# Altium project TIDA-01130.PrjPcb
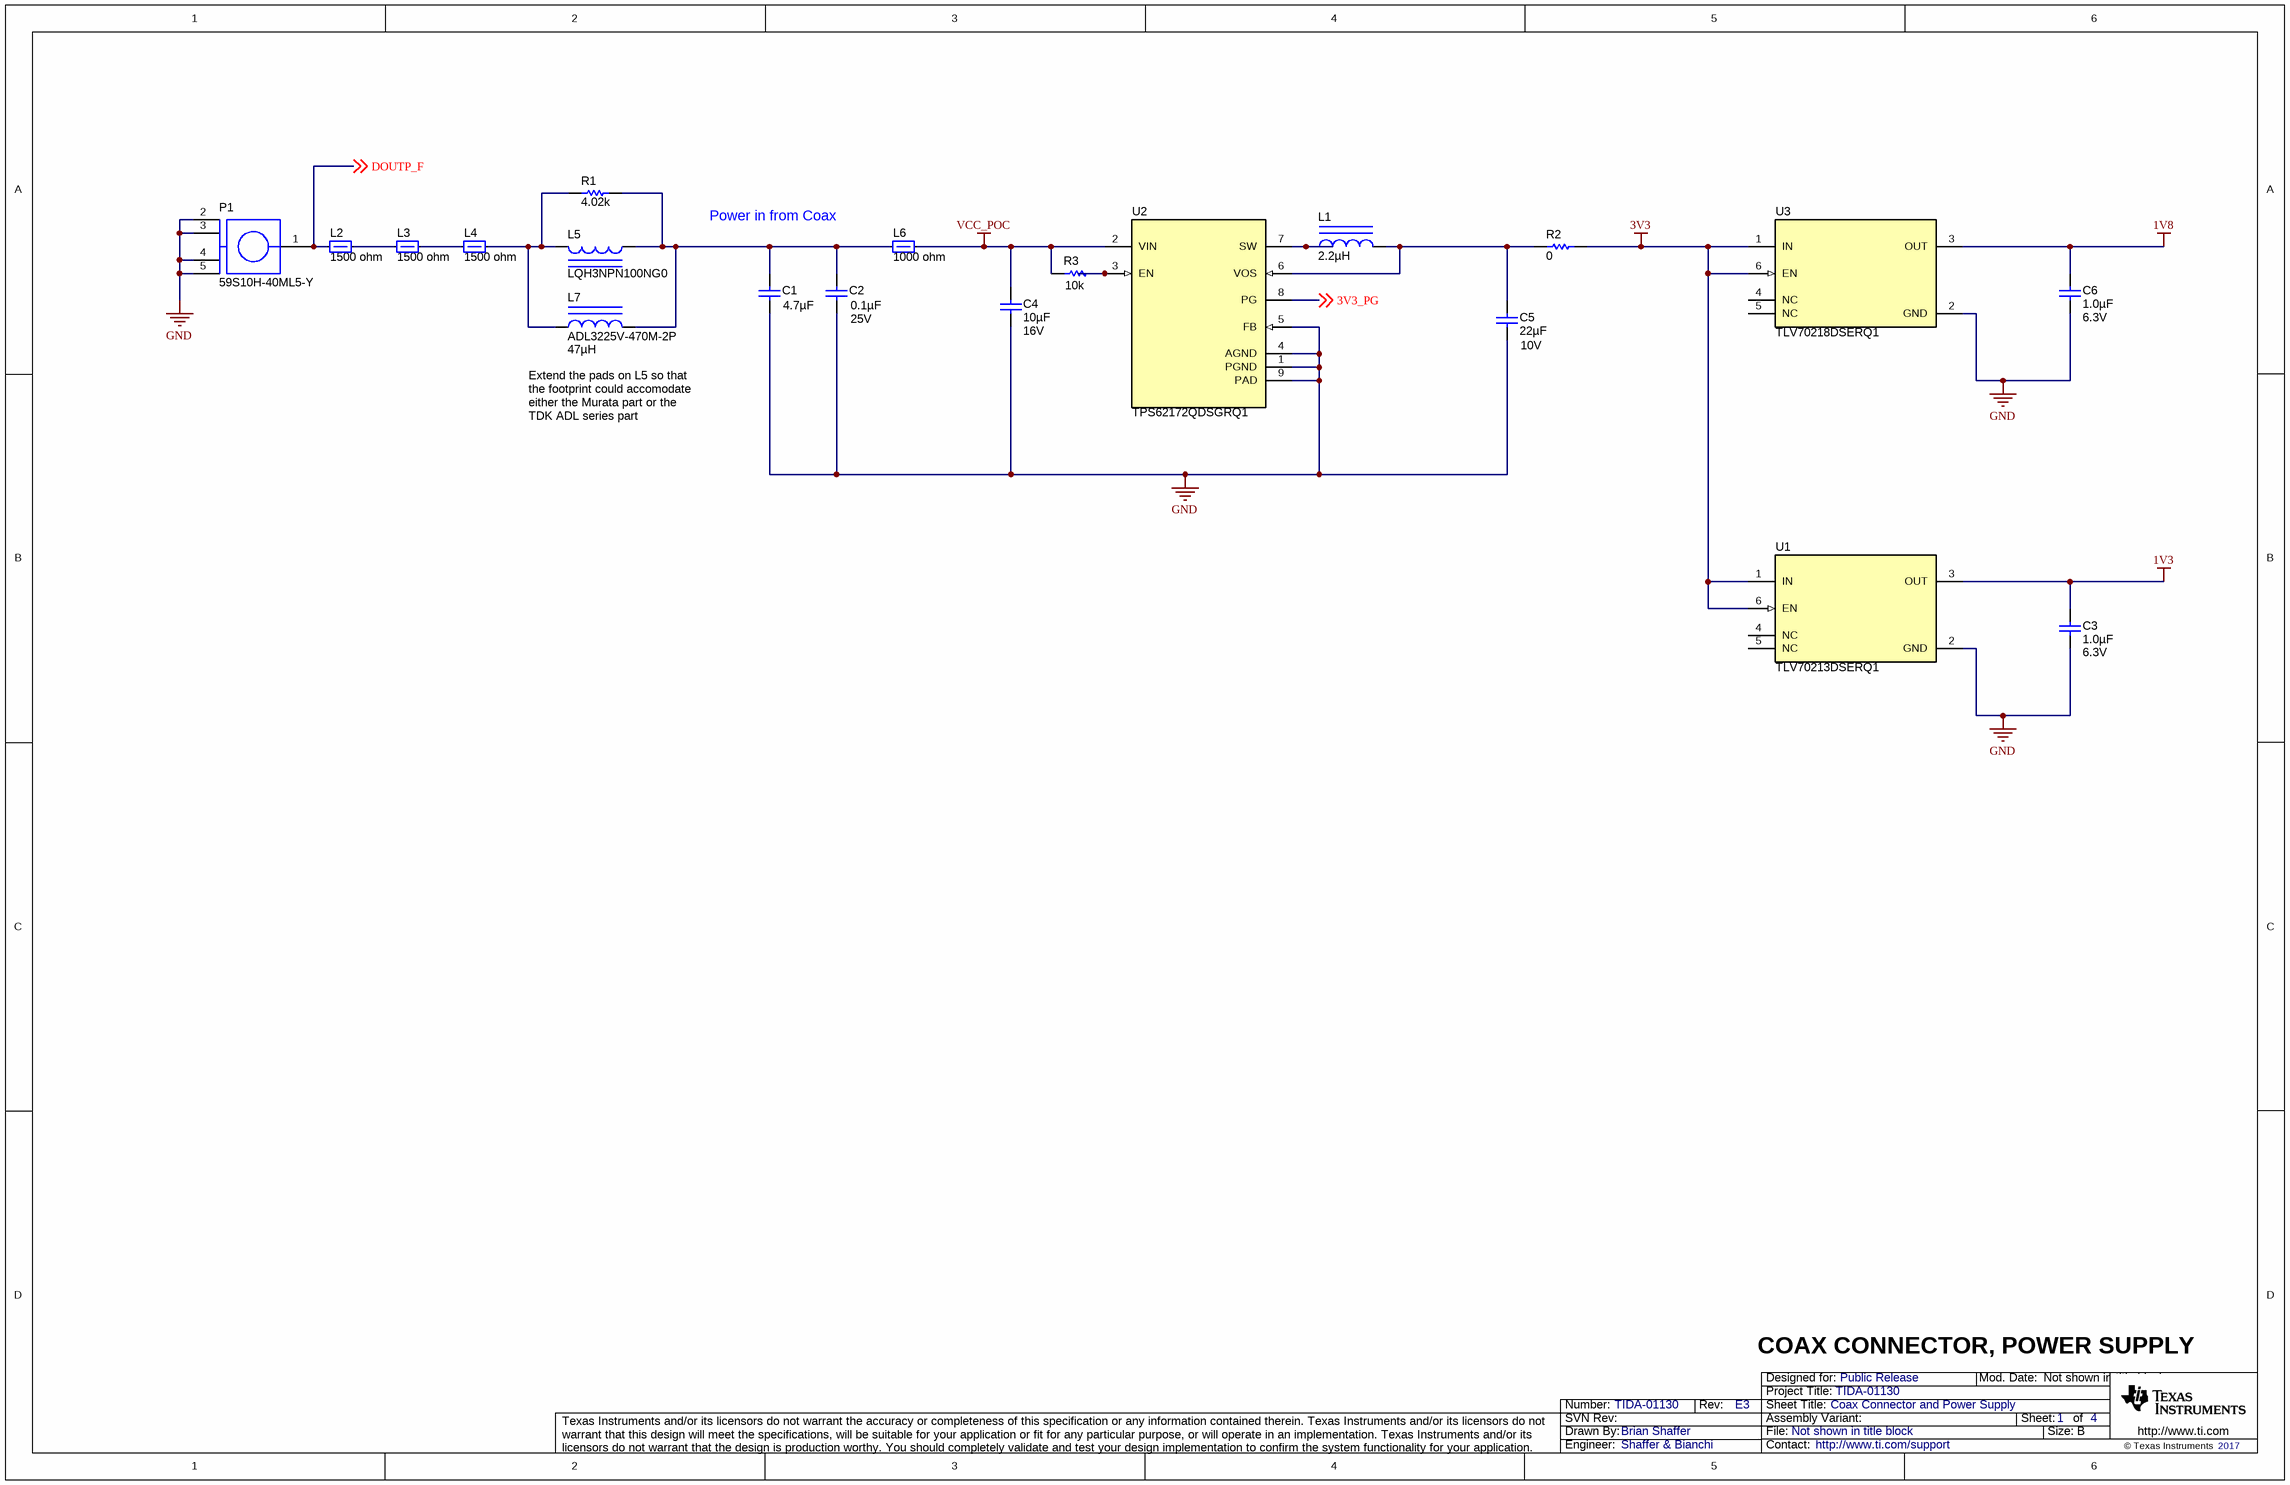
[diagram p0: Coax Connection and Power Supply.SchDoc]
CopyrightYear: 2017; PCB_Layout: Krypton Solutions; PCB_Rev: E3; PRJ_Customer: Public Release; PRJ_Engineer: Shaffer & Bianchi; PRJ_Number: TIDA-01130; PRJ_Title: TIDA-01130; SCH_Rev: E3; TechSupport: http://www.ti.com/support
4 sheets, 92 parts. Net scope: global (net labels, ports and power ports of the same name join across sheets).
Board file: TIDA-01130.PcbDoc
Sheets:
  Coax Connection and Power Supply.SchDoc
  Imager.SchDoc
  Serializer.SchDoc
  HDWR.SchDoc

## Sheet Coax Connection and Power Supply.SchDoc: Coax Connector and Power Supply
size 431 x 279 mm; Date: Not shown in title block; ApprovedBy: Not shown in title block; CheckedBy: Not shown in title block; Author: Not shown in title block; CompanyName: Not shown in title block; DrawnBy: Brian Shaffer; Engineer: Not shown in title block; Organization: Not shown in title block; Address1: Not shown in title block; Address2: Not shown in title block; Address3: Not shown in title block; Address4: Not shown in title block; DocumentNumber: 1; Revision: Use project parameter SCH_Rev; SheetNumber: 1; SheetTotal: 4; PageSetup: Record=PageOptions¦CenterHorizontal=True¦CenterVertical=True¦PrintScale=0.62¦XCorrection=1.00¦YCorrection=1.00¦PrintKind=0¦BorderSize=5000000¦LeftOffset=0¦BottomOffset=0¦Orientation=2¦PaperLength=1000¦PaperWidth=1000¦Scale=100¦PaperSource=15¦PrintQuality=600¦MediaType=1¦DitherType=10¦PrintScaleMode=1¦PaperKind=Letter (8.5 x 11")¦PaperIndex=1

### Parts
C1  value 4.7µF  [0805L]  (hidden comment: CGA4J1X7R1E475M125AC)
C2  value 0.1µF  VDC_V: 25V  [0402L]  (hidden comment: C1005X7R1E104K050BB)
C3  value 1.0µF  VDC_V: 6.3V  [0402L]  (hidden comment: CL05B105KQ5NQNC)
C4  ValueDisplayed: 10µF  Value2: 16V  [0805L]  (hidden comment: CL21B106KOQNNNE)
C5  ValueDisplayed: 22µF  VDC_V: 10V  [1206L]  (hidden comment: GRM31CR71A226KE15L)
C6  value 1.0µF  VDC_V: 6.3V  [0402L]  (hidden comment: CL05B105KQ5NQNC)
L1  ValueDisplayed: 2.2µH  [XPL2010]  (hidden comment: XPL2010-222MLB)
L2  value 1500 ohm  [0603L]  (hidden comment: BLM18HE152SN1D)
L3  value 1500 ohm  [0603L]  (hidden comment: BLM18HE152SN1D)
L4  value 1500 ohm  [0603L]  (hidden comment: BLM18HE152SN1D)
L5  LQH3NPN100NG0  [LQH3NP_G0]
L6  value 1000 ohm  [0603L]  (hidden comment: BLM18AG102SN1D)
L7  ADL3225V-470M-2P  ValueDisplayed: 47µH  [ADL3225V]
P1  59S10H-40ML5-Y  [59S10H-40ML5-Y]
R1  ValueDisplayed: 4.02k  [0603L]  (hidden comment: CRCW06034K02FKEA)
R2  value 0  [0402L]  (hidden comment: CRCW04020000Z0ED)
R3  value 10k  [0402L]  (hidden comment: CRCW040210K0JNED)
U1  TLV70213DSERQ1  [DSE0006A]
U2  TPS62172QDSGRQ1  [DSG0008A]
U3  TLV70218DSERQ1  [DSE0006A]

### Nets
1V3: C3.1 U1.3(OUT)
1V8: C6.1 U3.3(OUT)
3V3: R2.1 U1.1(IN) U1.6(EN) U3.1(IN) U3.6(EN)
GND: C1.2 C2.2 C3.2 C4.2 C5.2 C6.2 P1.2 P1.3 P1.4 P1.5 U1.2(GND) U2.1(PGND) U2.4(AGND) U2.5(FB) U2.9(PAD) U3.2(GND)
VCC_POC: C4.1 L6.2 R3.2 U2.2(VIN)
3V3_PG: U2.8(PG) ; off-sheet 3V3_PG
DOUTP_F: L2.1 P1.1 ; off-sheet DOUTP_F
NetC1_1: C1.1 C2.1 L5.1 L6.1 L7.2 R1.1
NetC5_1: C5.1 L1.2 R2.2 U2.6(VOS)
NetL1_1: L1.1 U2.7(SW)
NetL2_2: L2.2 L3.1
NetL3_2: L3.2 L4.1
NetL4_2: L4.2 L5.2 L7.1 R1.2
NetR3_1: R3.1 U2.3(EN)

Not connected (* = marked no-connect by the designer): U1 4(NC) 5(NC); U3 4(NC) 5(NC)

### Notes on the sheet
- (near L6) Power in from Coax
- (near L7) Extend the pads on L5 so that the footprint could accomodate either the Murata part or the TDK ADL series part
- COAX CONNECTOR, POWER SUPPLY

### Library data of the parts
C1 = C2012X7R1E474K: CAP, CERM, 4.7uF, 25V, +/-20%, X7R, 0805; Manufacturer: TDK Corporation; Tolerance_%: ±20%
C2 = C1005X7R1E103K: CAP, CERM, 0.1uF, 25V, +/-10%, X7R, 0402; Manufacturer: TDK Corporation; Tolerance_%: ±10%
C3 C6 = Capacitor: CAP CER 1UF 6.3V 10% X7R 0402; Manufacturer: Samsung Electro-Mechanics America, Inc; Polarized: N; U/M: EA
C4 = CL21B106KOQNNNE: CAP, CERM, 10 µF, 16 V, +/- 10%, X7R, 0805; Manufacturer: Samsung Electro-Mechanics; Polarized: N; CompType: Capacitor; Value: 10uF; U/M: EA; Cap_F: 0.00001; Tolerance_%: 10; Value1: Unknown; VDC_V: 16; TaMin_C: -55; TaMax_C: 125; Cap_Case: 0805; SizeArea_mm2: 2.5; SizeAreaWB_mm2: 6.75; SizeX_mm: 2; SizeY_mm: 1.25; SizeZ_mm: 1.45; AEC Category: Q200
C5 = GRM31CR71A226KE15L: CAP, CERM, 22uF, 10V, +/-10%, X7R, 1206; Manufacturer: MuRata; Polarized: N; CompType: Capacitor; U/M: EA; Cap_F: 0.000022; Tolerance_%: 10; Value1: Unknown; TaMin_C: -55; TaMax_C: 125; Cap_Case: 1206
L1 = XPL2010-222MLB: Inductor, Shielded, Composite, 2.2 µH, 1.3 A, 0.16 ohm, SMD; Manufacturer: Coilcraft; Value: 2.2uH; Ind_H: 2.2E-6; Imax_A: 1.3; Irms: 1.3A @ 40C rise; Isat: 1.35A @ 30% inductance drop; DCR_ohm: 0.16; Value2: 1.3A; SizeAreaWB_mm2: 8.7; SizeArea_mm2: 3.8; SizeX_mm: 2; SizeY_mm: 1.9; SizeZ_mm: 1; AEC Category: Q200; Green_Lifecycle: Not Set; Green_REACh: Incomplete
L2 L3 = BLM18HE152SN1D: Ferrite Bead, 1500 ohm @ 100 MHz, 0.5 A, 0603; Manufacturer: MuRata; Imax_A: 0.5; Value1: 0.5 ohm; Value2: 0.5A; ZTyp@100MHz_Ohm: 1500; SizeAreaWB_mm2: 4.68; SizeArea_mm2: 1.28; SizeX_mm: 1.6; SizeY_mm: 0.8; SizeZ_mm: 1
L4 = BLM18HE152SN1D: Ferrite Bead, 1500 ohm @ 100 MHz, 0.5 A, 0603; Manufacturer: MuRata; Value1: 0.5 ohm; Value2: 0.5A; SizeArea_mm2: 1.28; SizeX_mm: 1.6; SizeY_mm: 0.8; SizeZ_mm: 1; Imax_A: 0.5; SizeAreaWB_mm2: 4.68; ZTyp@100MHz_Ohm: 1500
L5 = LQH3NPN100NG0: Inductor, Wirewound, Ferrite, 10 µH, 0.5 A, 0.57 ohm, SMD; Manufacturer: MuRata; Value: 10uH; Ind_H: 10.0E-6; ValueDisplayed: 10µH; Imax_A: 0.5; Irms: 0.63A @ 40C rise; Isat: 0.5A @ 30% inductance drop; DCR_ohm: 0.57; Value2: 0.5A
L6 = BLM18AG102SN1D: Ferrite Bead, 1000 ohm @ 100 MHz, 0.4 A, 0603; Manufacturer: MuRata; Imax_A: 0.4; DCR_ohm: 0.5; Value1: 0.5 ohm; Value2: 0.4A; ZTyp@100MHz_Ohm: 1000
L7 = ADL3225V-470M-2P: Inductor, Wirewound, 47 µH, 0.35 A, 1.3 ohm, SMD; Manufacturer: TDK; Value: 47uH; Ind_H: 47.0E-6; Imax_A: 0.35; Irms: 0.385A @ 40C rise; Isat: 0.35A @ 30% inductance drop; DCR_ohm: 1.3; Value1: 1.3 ohm; Value2: 0.35A; SizeAreaWB_mm2: 14.7; SizeArea_mm2: 8; SizeX_mm: 3.2; SizeY_mm: 2.5; SizeZ_mm: 2.4; AEC Category: Q200
P1 = 59S10H-40ML5-Y: Straight Plug PCB; Manufacturer: Rosenberger; SymbolVersion: use current date i.e. 2008-05-20; SymbolCreator: Use a-id; CompType: SMA connector; U/M: EA, IN, or GM
R1 = CRCW06034K02FKEA: RES, 4.02 k, 1%, 0.1 W, 0603; Manufacturer: Vishay-Dale; CompType: Resistor; Value: 4.02k; Res_ohm: 4020; Value_Code: 4k02; Tolerance_%: 1; Power_W: 0.1; Value2: 0.1W; VDC_V: 75; TempCo: 100 ppm/C; EIA_Code: E96; U/M: EA
R2 = CRCW04020000Z0ED: RES, 0 ohm, 5%, 0.063W, 0402; Manufacturer: Vishay-Dale; CompType: Resistor; Value_Code: 0000; Tolerance_%: 5; Power_W: 0.063; VDC_V: 50; TempCo: 200 ppm/C; EIA_Code: E24; U/M: EA
R3 = CRCW040210K0JNED: RES, 10k ohm, 5%, 0.063W, 0402; Manufacturer: Vishay-Dale; CompType: Resistor; Res_ohm: 10000; Value_Code: 10k0; Tolerance_%: 5; Power_W: 0.063; VDC_V: 50; TempCo: 200 ppm/C; EIA_Code: E24; U/M: EA
U1 = TLV70213DSERQ1: Automotive 300mA, Low IQ, Low-Dropout Regulator, DSE0006A (WSON-6); Manufacturer: Texas Instruments; SymbolCreator: Altium; SizeArea_mm2: 2.25; SizeAreaWB_mm2: 6.25; SizeX_mm: 1.5; SizeZ_mm: 0.8; CompType: IC; U/M: EA
U2 = TPS62172QDSGRQ1: 3-V to17-V 0.5-A Step-Down Converters with DCS-Control™, DSG0008A (WSON-8); Manufacturer: Texas Instruments; Alternate PartNumber: TPS62172QDSGTQ1; SymbolCreator: Altium; SizeArea_mm2: 4; SizeAreaWB_mm2: 9; SizeX_mm: 2; SizeZ_mm: 0.8; CompType: IC; U/M: EA
U3 = TLV70218DSERQ1: Automotive 300mA, Low IQ, Low-Dropout Regulator, DSE0006A (WSON-6); Manufacturer: Texas Instruments; SymbolCreator: Altium; SizeArea_mm2: 2.25; SizeAreaWB_mm2: 6.25; SizeX_mm: 1.5; SizeZ_mm: 0.8; CompType: IC; U/M: EA

## Sheet Imager.SchDoc: Image Sensor
size 431 x 279 mm; Date: Not shown in title block; ApprovedBy: Not shown in title block; CheckedBy: Not shown in title block; Author: Not shown in title block; CompanyName: Not shown in title block; DrawnBy: Brian Shaffer; Engineer: Not shown in title block; Organization: Not shown in title block; Address1: Not shown in title block; Address2: Not shown in title block; Address3: Not shown in title block; Address4: Not shown in title block; DocumentNumber: 2; Revision: Use project parameter SCH_Rev; SheetNumber: 2; SheetTotal: 4; PageSetup: Record=PageOptions¦CenterHorizontal=True¦CenterVertical=True¦PrintScale=0.96¦XCorrection=1.00¦YCorrection=1.00¦PrintKind=0¦BorderSize=5000000¦LeftOffset=0¦BottomOffset=0¦Orientation=2¦PaperLength=4318¦PaperWidth=2794¦Scale=100¦PaperSource=15¦PrintQuality=600¦MediaType=1¦DitherType=10¦PrintScaleMode=1¦PaperKind=Tabloid (11 x 17")¦PaperIndex=17
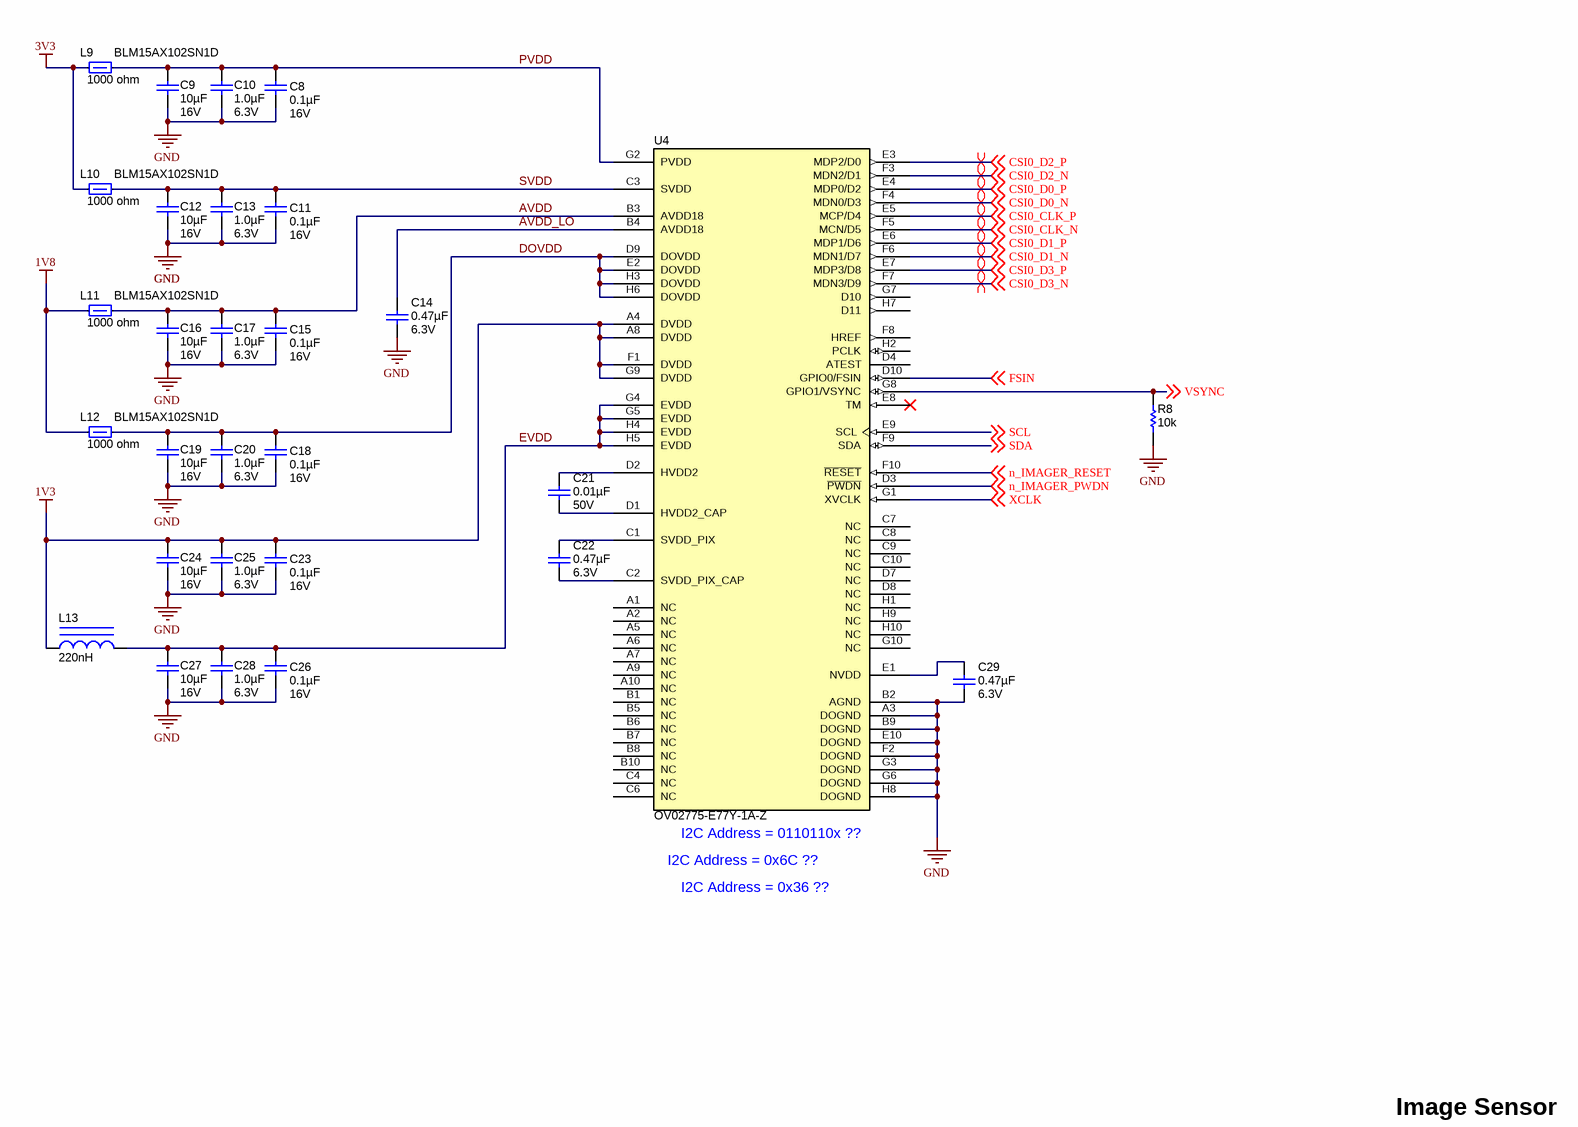
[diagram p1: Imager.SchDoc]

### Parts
C8  ValueDisplayed: 0.1µF  Value2: 16V  [0402S]  (hidden comment: 0402YC104KAT2A)
C9  ValueDisplayed: 10µF  Value2: 16V  [0805L]  (hidden comment: CL21B106KOQNNNE)
C10  value 1.0µF  VDC_V: 6.3V  [0402L]  (hidden comment: CL05B105KQ5NQNC)
C11  ValueDisplayed: 0.1µF  Value2: 16V  [0402S]  (hidden comment: 0402YC104KAT2A)
C12  ValueDisplayed: 10µF  Value2: 16V  [0805L]  (hidden comment: CL21B106KOQNNNE)
C13  value 1.0µF  VDC_V: 6.3V  [0402L]  (hidden comment: CL05B105KQ5NQNC)
C14  ValueDisplayed: 0.47µF  Value2: 6.3V  [0402L]  (hidden comment: JMK105B7474KVHF)
C15  ValueDisplayed: 0.1µF  Value2: 16V  [0402S]  (hidden comment: 0402YC104KAT2A)
C16  ValueDisplayed: 10µF  Value2: 16V  [0805_HV1]  (hidden comment: CL21B106KOQNNNE)
C17  value 1.0µF  VDC_V: 6.3V  [0402L]  (hidden comment: CL05B105KQ5NQNC)
C18  ValueDisplayed: 0.1µF  Value2: 16V  [0402S]  (hidden comment: 0402YC104KAT2A)
C19  ValueDisplayed: 10µF  Value2: 16V  [0805L]  (hidden comment: CL21B106KOQNNNE)
C20  value 1.0µF  VDC_V: 6.3V  [0402L]  (hidden comment: CL05B105KQ5NQNC)
C21  ValueDisplayed: 0.01µF  Value2: 50V  [0402S]  (hidden comment: GRM155R71H103KA88D)
C22  ValueDisplayed: 0.47µF  Value2: 6.3V  [0402S]  (hidden comment: JMK105B7474KVHF)
C23  ValueDisplayed: 0.1µF  Value2: 16V  [0402S]  (hidden comment: 0402YC104KAT2A)
C24  ValueDisplayed: 10µF  Value2: 16V  [0805L]  (hidden comment: CL21B106KOQNNNE)
C25  value 1.0µF  VDC_V: 6.3V  [0402L]  (hidden comment: CL05B105KQ5NQNC)
C26  ValueDisplayed: 0.1µF  Value2: 16V  [0402S]  (hidden comment: 0402YC104KAT2A)
C27  ValueDisplayed: 10µF  Value2: 16V  [0805L]  (hidden comment: CL21B106KOQNNNE)
C28  value 1.0µF  VDC_V: 6.3V  [0402L]  (hidden comment: CL05B105KQ5NQNC)
C29  ValueDisplayed: 0.47µF  Value2: 6.3V  [0402S]  (hidden comment: JMK105B7474KVHF)
L9  value 1000 ohm  [0402S]  (hidden comment: BLM15AX102SN1D)
L10  value 1000 ohm  [0402S]  (hidden comment: BLM15AX102SN1D)
L11  value 1000 ohm  [0402S]  (hidden comment: BLM15AX102SN1D)
L12  value 1000 ohm  [0402S]  (hidden comment: BLM15AX102SN1D)
L13  ValueDisplayed: 220nH  [NLCV32]  (hidden comment: NLCV32T-R22M-PFR)
R8  value 10k  [0402S]  (hidden comment: CRCW040210K0JNED)
U4  OV02775-E77Y-1A-Z  [aCSP-77]

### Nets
1V3: C23.1 C24.1 C25.1 L13.1 U4.A4(DVDD) U4.A8(DVDD) U4.F1(DVDD) U4.G9(DVDD)
1V8: L11.1 L12.1
3V3: L9.1 L10.1
GND: C8.2 C9.2 C10.2 C11.2 C12.2 C13.2 C14.2 C15.2 C16.2 C17.2 C18.2 C19.2 C20.2 C23.2 C24.2 C25.2 C26.2 C27.2 C28.2 C29.2 R8.1 U4.A3(DOGND) U4.B2(AGND) U4.B9(DOGND) U4.E10(DOGND) U4.F2(DOGND) U4.G3(DOGND) U4.G6(DOGND) U4.H8(DOGND)
AVDD: C15.1 C16.1 C17.1 L11.2 U4.B3(AVDD18)
AVDD_LO: C14.1 U4.B4(AVDD18)
CSI0_CLK_N: U4.F5(MCN/D5) ; off-sheet CSI0_CLK_N
CSI0_CLK_P: U4.E5(MCP/D4) ; off-sheet CSI0_CLK_P
CSI0_D0_N: U4.F4(MDN0/D3) ; off-sheet CSI0_D0_N
CSI0_D0_P: U4.E4(MDP0/D2) ; off-sheet CSI0_D0_P
CSI0_D1_N: U4.F6(MDN1/D7) ; off-sheet CSI0_D1_N
CSI0_D1_P: U4.E6(MDP1/D6) ; off-sheet CSI0_D1_P
CSI0_D2_N: U4.F3(MDN2/D1) ; off-sheet CSI0_D2_N
CSI0_D2_P: U4.E3(MDP2/D0) ; off-sheet CSI0_D2_P
CSI0_D3_N: U4.F7(MDN3/D9) ; off-sheet CSI0_D3_N
CSI0_D3_P: U4.E7(MDP3/D8) ; off-sheet CSI0_D3_P
DOVDD: C18.1 C19.1 C20.1 L12.2 U4.D9(DOVDD) U4.E2(DOVDD) U4.H3(DOVDD) U4.H6(DOVDD)
EVDD: C26.1 C27.1 C28.1 L13.2 U4.G4(EVDD) U4.G5(EVDD) U4.H4(EVDD) U4.H5(EVDD)
FSIN: U4.D10(GPIO0/FSIN) ; off-sheet FSIN
n_IMAGER_PWDN: U4.D3(~{PWDN}) ; off-sheet n_IMAGER_PWDN
n_IMAGER_RESET: U4.F10(~{RESET}) ; off-sheet n_IMAGER_RESET
PVDD: C8.1 C9.1 C10.1 L9.2 U4.G2(PVDD)
SCL: U4.E9(SCL) ; off-sheet SCL
SDA: U4.F9(SDA) ; off-sheet SDA
SVDD: C11.1 C12.1 C13.1 L10.2 U4.C3(SVDD)
VSYNC: R8.2 U4.G8(GPIO1/VSYNC) ; off-sheet VSYNC
XCLK: U4.G1(XVCLK) ; off-sheet XCLK
NetC21_1: C21.1 U4.D2(HVDD2)
NetC21_2: C21.2 U4.D1(HVDD2_CAP)
NetC22_1: C22.1 U4.C1(SVDD_PIX)
NetC22_2: C22.2 U4.C2(SVDD_PIX_CAP)
NetC29_1: C29.1 U4.E1(NVDD)

Not connected (* = marked no-connect by the designer): U4 A1(NC) A2(NC) A5(NC) A6(NC) A7(NC) A9(NC) A10(NC) B1(NC) B5(NC) B6(NC) B7(NC) B8(NC) B10(NC) C4(NC) C6(NC) C7(NC) C8(NC) C9(NC) C10(NC) D4(ATEST) D7(NC) D8(NC) E8(TM)* F8(HREF) G7(D10) G10(NC) H1(NC) H2(PCLK) H7(D11) H9(NC) H10(NC)

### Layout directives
differential pair: CSI0_CLK_N, CSI0_CLK_P, CSI0_D0_N, CSI0_D0_P, CSI0_D1_N, CSI0_D1_P, CSI0_D2_N, CSI0_D2_P, CSI0_D3_N, CSI0_D3_P

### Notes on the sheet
- (near U4) I2C Address = 0110110x ??
- I2C Address = 0x6C ??
- I2C Address = 0x36 ??
- Image Sensor

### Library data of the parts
C8 C11 C15 C18 C23 C26 = 0402YC104KAT2A: CAP, CERM, 0.1 µF, 16 V, +/- 10%, X7R, 0402; Manufacturer: AVX; Polarized: N; CompType: Capacitor; Value: 0.1uF; U/M: EA; Cap_F: 0.0000001; Tolerance_%: 10; Value1: Unknown; VDC_V: 16; TaMin_C: -55; TaMax_C: 125; Cap_Case: 0402; SizeArea_mm2: 0.5; SizeAreaWB_mm2: 3; SizeX_mm: 1; SizeZ_mm: 0.6; AEC Category: Q200
C9 C12 C16 C19 C24 C27 = CL21B106KOQNNNE: as C4 on sheet Coax Connection and Power Supply
C10 C13 C17 C20 C25 C28 = Capacitor: as C3 on sheet Coax Connection and Power Supply
C14 C22 C29 = JMK105B7474KVHF: CAP, CERM, 0.47 µF, 6.3 V, +/- 10%, X7R, 0402; Manufacturer: Taiyo Yuden; Polarized: N; CompType: Capacitor; Value: 0.47uF; U/M: EA; Cap_F: 0.00000047; Tolerance_%: 10; Value1: Unknown; VDC_V: 6.3; TaMin_C: -55; TaMax_C: 125; Cap_Case: 0402; SizeArea_mm2: 0.5; SizeAreaWB_mm2: 3; SizeX_mm: 1; SizeZ_mm: 0.6; AEC Category: Q200
C21 = GRM155R71H103KA88D: CAP, CERM, 0.01 µF, 50 V, +/- 10%, X7R, 0402; Manufacturer: MuRata; Polarized: N; CompType: Capacitor; Value: 0.01uF; U/M: EA; Cap_F: 0.00000001; Tolerance_%: 10; Value1: Unknown; VDC_V: 50; TaMin_C: -55; TaMax_C: 125; Cap_Case: 0402; SizeArea_mm2: 0.5; SizeAreaWB_mm2: 3; SizeX_mm: 1; SizeZ_mm: 0.6; AEC Category: Q200
L9-L12 = BLM15AX102SN1D: Ferrite Bead, 1000 ohm @ 100 MHz, 0.35 A, 0402; Manufacturer: MuRata; Imax_A: 0.35; DCR_ohm: 0.49; Value1: 0.49 ohm; Value2: 0.35A; ZTyp@100MHz_Ohm: 1000
L13 = NLCV32T-R22M-PFR: Inductor, Wirewound, Ferrite, 220 nH, 2.4 A, 0.027 ohm, SMD; Manufacturer: TDK; Value: 220nH; Ind_H: 220.0E-9; Imax_A: 2.4; Irms: 2.4A @ 20C rise; Isat: 2.4A @ 10% inductance drop; DCR_ohm: 0.027; Value2: 2.4A; AEC Category: Q200
R8 = CRCW040210K0JNED: as R3 on sheet Coax Connection and Power Supply
U4 = OV02775-E77Y-1A-Z: Color CMOS 1080p (1920x1080) high dynamicrange(HDR) high definition image sensor, aCSP-77; Manufacturer: OmniVision Technologies; SymbolCreator: Altium

## Sheet Serializer.SchDoc: Serializer
size 431 x 279 mm; Date: Not shown in title block; ApprovedBy: Not shown in title block; CheckedBy: Not shown in title block; Author: Not shown in title block; CompanyName: Not shown in title block; DrawnBy: Brian Shaffer; Engineer: Not shown in title block; Organization: Not shown in title block; Address1: Not shown in title block; Address2: Not shown in title block; Address3: Not shown in title block; Address4: Not shown in title block; DocumentNumber: 3; Revision: Use project parameter SCH_Rev; SheetNumber: 3; SheetTotal: 4; PageSetup: Record=PageOptions¦CenterHorizontal=True¦CenterVertical=True¦PrintScale=0.64¦XCorrection=1.00¦YCorrection=1.00¦PrintKind=0¦BorderSize=5000000¦LeftOffset=0¦BottomOffset=0¦Orientation=2¦PaperLength=4318¦PaperWidth=2794¦Scale=100¦PaperSource=15¦PrintQuality=600¦MediaType=1¦DitherType=10¦PrintScaleMode=1¦PaperKind=Tabloid (11 x 17")¦PaperIndex=17
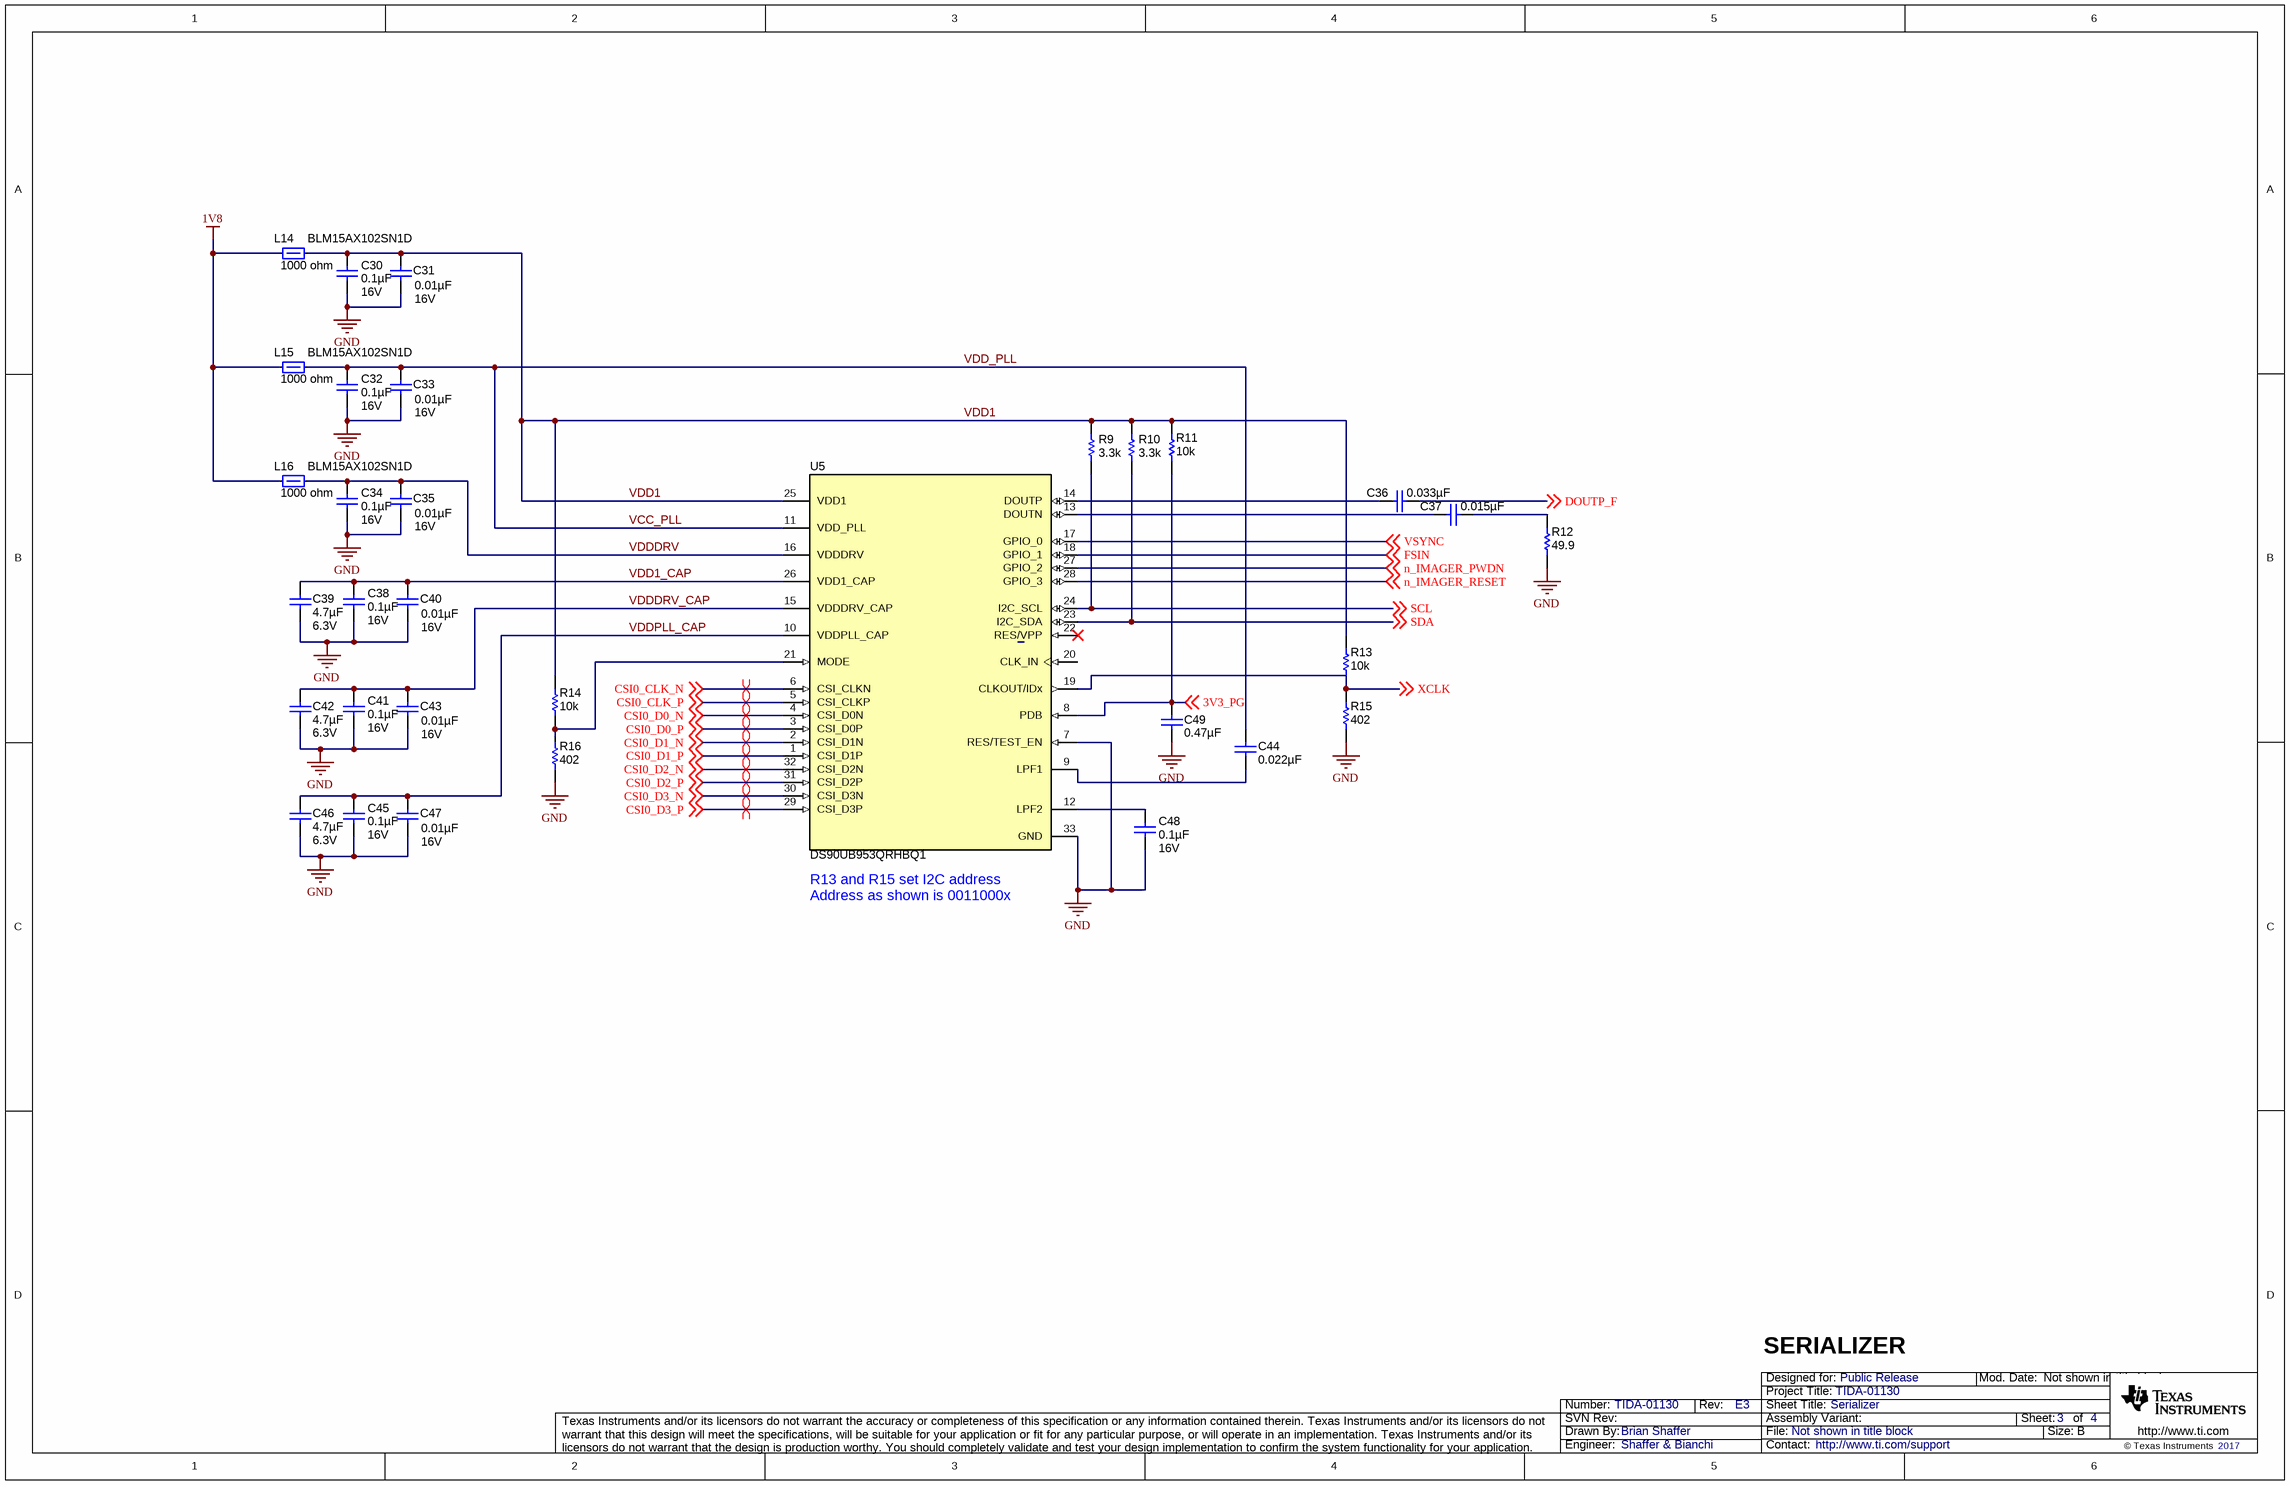
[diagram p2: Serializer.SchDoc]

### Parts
C30  ValueDisplayed: 0.1µF  Value2: 16V  [0402S]  (hidden comment: 0402YC104KAT2A)
C31  ValueDisplayed: 0.01µF  Value2: 16V  [0402S]  (hidden comment: GRM155R71C103KA01D)
C32  ValueDisplayed: 0.1µF  Value2: 16V  [0402S]  (hidden comment: 0402YC104KAT2A)
C33  ValueDisplayed: 0.01µF  Value2: 16V  [0402S]  (hidden comment: GRM155R71C103KA01D)
C34  ValueDisplayed: 0.1µF  Value2: 16V  [0402S]  (hidden comment: 0402YC104KAT2A)
C35  ValueDisplayed: 0.01µF  Value2: 16V  [0402S]  (hidden comment: GRM155R71C103KA01D)
C36  ValueDisplayed: 0.033µF  [0402S]  (hidden comment: CGA2B3X7R1H333K050BB)
C37  ValueDisplayed: 0.015µF  [0402S]  (hidden comment: CGA2B3X7R1H153K050BB)
C38  ValueDisplayed: 0.1µF  Value2: 16V  [0402S]  (hidden comment: 0402YC104KAT2A)
C39  ValueDisplayed: 4.7µF  Value2: 6.3V  [0603S]  (hidden comment: JMK107BB7475MA-T)
C40  ValueDisplayed: 0.01µF  Value2: 16V  [0402S]  (hidden comment: GRM155R71C103KA01D)
C41  ValueDisplayed: 0.1µF  Value2: 16V  [0402S]  (hidden comment: 0402YC104KAT2A)
C42  ValueDisplayed: 4.7µF  Value2: 6.3V  [0603S]  (hidden comment: JMK107BB7475MA-T)
C43  ValueDisplayed: 0.01µF  Value2: 16V  [0402S]  (hidden comment: GRM155R71C103KA01D)
C44  ValueDisplayed: 0.022µF  [0402S]  (hidden comment: GRM155R70J223KA01D)
C45  ValueDisplayed: 0.1µF  Value2: 16V  [0402S]  (hidden comment: 0402YC104KAT2A)
C46  ValueDisplayed: 4.7µF  Value2: 6.3V  [0603S]  (hidden comment: JMK107BB7475MA-T)
C47  ValueDisplayed: 0.01µF  Value2: 16V  [0402S]  (hidden comment: GRM155R71C103KA01D)
C48  ValueDisplayed: 0.1µF  Value2: 16V  [0402S]  (hidden comment: 0402YC104KAT2A)
C49  ValueDisplayed: 0.47µF  [0402L]  (hidden comment: GRM155R60J474KE19D)
L14  value 1000 ohm  [0402S]  (hidden comment: BLM15AX102SN1D)
L15  value 1000 ohm  [0402S]  (hidden comment: BLM15AX102SN1D)
L16  value 1000 ohm  [0402S]  (hidden comment: BLM15AX102SN1D)
R9  ValueDisplayed: 3.3k  [0402S]  (hidden comment: CRCW04023K30JNED)
R10  ValueDisplayed: 3.3k  [0402S]  (hidden comment: CRCW04023K30JNED)
R11  value 10k  [0402S]  (hidden comment: CRCW040210K0JNED)
R12  value 49.9  [0402L]  (hidden comment: CRCW040249R9FKED)
R13  value 10k  [0402S]  (hidden comment: CRCW040210K0JNED)
R14  value 10k  [0402S]  (hidden comment: CRCW040210K0JNED)
R15  ValueDisplayed: 402  [0402S]  (hidden comment: CRCW0402402RFKED)
R16  ValueDisplayed: 402  [0402S]  (hidden comment: CRCW0402402RFKED)
U5  DS90UB953QRHBQ1  [RHB0032B]

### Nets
1V8: L14.1 L15.1 L16.1
GND: C30.2 C31.2 C32.2 C33.2 C34.2 C35.2 C38.2 C39.1 C40.2 C41.2 C42.1 C43.2 C45.2 C46.1 C47.2 C48.2 C49.2 R12.1 R15.1 R16.1 U5.7(RES/TEST_EN) U5.33(GND)
3V3_PG: C49.1 R11.1 U5.8(PDB) ; off-sheet 3V3_PG
CSI0_CLK_N: U5.6(CSI_CLKN) ; off-sheet CSI0_CLK_N
CSI0_CLK_P: U5.5(CSI_CLKP) ; off-sheet CSI0_CLK_P
CSI0_D0_N: U5.4(CSI_D0N) ; off-sheet CSI0_D0_N
CSI0_D0_P: U5.3(CSI_D0P) ; off-sheet CSI0_D0_P
CSI0_D1_N: U5.2(CSI_D1N) ; off-sheet CSI0_D1_N
CSI0_D1_P: U5.1(CSI_D1P) ; off-sheet CSI0_D1_P
CSI0_D2_N: U5.32(CSI_D2N) ; off-sheet CSI0_D2_N
CSI0_D2_P: U5.31(CSI_D2P) ; off-sheet CSI0_D2_P
CSI0_D3_N: U5.30(CSI_D3N) ; off-sheet CSI0_D3_N
CSI0_D3_P: U5.29(CSI_D3P) ; off-sheet CSI0_D3_P
DOUTP_F: C36.1 ; off-sheet DOUTP_F
FSIN: U5.18(GPIO_1) ; off-sheet FSIN
n_IMAGER_PWDN: U5.27(GPIO_2) ; off-sheet n_IMAGER_PWDN
n_IMAGER_RESET: U5.28(GPIO_3) ; off-sheet n_IMAGER_RESET
SCL: R9.1 U5.24(I2C_SCL) ; off-sheet SCL
SDA: R10.1 U5.23(I2C_SDA) ; off-sheet SDA
VCC_PLL: C32.1 C33.1 C44.1 L15.2 U5.11(VDD_PLL)  [also labelled VDD_PLL]
VDD1: C30.1 C31.1 L14.2 R9.2 R10.2 R11.2 R13.2 R14.2 U5.25(VDD1)
VDD1_CAP: C38.1 C39.2 C40.1 U5.26(VDD1_CAP)
VDDDRV: C34.1 C35.1 L16.2 U5.16(VDDDRV)
VDDDRV_CAP: C41.1 C42.2 C43.1 U5.15(VDDDRV_CAP)
VDDPLL_CAP: C45.1 C46.2 C47.1 U5.10(VDDPLL_CAP)
VSYNC: U5.17(GPIO_0) ; off-sheet VSYNC
XCLK: R13.1 R15.2 U5.19(CLKOUT/IDx) ; off-sheet XCLK
NetC36_2: C36.2 U5.14(DOUTP)
NetC37_1: C37.1 R12.2
NetC37_2: C37.2 U5.13(DOUTN)
NetC44_2: C44.2 U5.9(LPF1)
NetC48_1: C48.1 U5.12(LPF2)
NetR14_1: R14.1 R16.2 U5.21(MODE)

Not connected (* = marked no-connect by the designer): U5 20(CLK_IN) 22(RES/VPP)*

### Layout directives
differential pair: CSI0_CLK_N, CSI0_CLK_P, CSI0_D0_N, CSI0_D0_P, CSI0_D1_N, CSI0_D1_P, CSI0_D2_N, CSI0_D2_P, CSI0_D3_N, CSI0_D3_P

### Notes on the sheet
- (near U5) R13 and R15 set I2C address
  Address as shown is 0011000x
- SERIALIZER

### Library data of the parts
C30 C32 C34 C38 C41 C45 C48 = 0402YC104KAT2A: as C8 on sheet Imager
C31 C33 C35 C40 C43 C47 = GRM155R71C103KA01D: CAP, CERM, 0.01uF, 16V, +/-10%, X7R, 0402; Manufacturer: MuRata; Polarized: N; CompType: Capacitor; U/M: EA; Cap_F: 0.00000001; Tolerance_%: 10; Value1: Unknown; VDC_V: 16; TaMin_C: -55; TaMax_C: 125; Cap_Case: 0402
C36 = CGA2B3X7R1H333K050BB: CAP, CERM, 0.033 µF, 50 V, +/- 10%, X7R, 0402; Manufacturer: TDK; Polarized: N; CompType: Capacitor; Value: 0.033uF; U/M: EA; Cap_F: 0.000000033; Tolerance_%: 10; Value1: Unknown; VDC_V: 50; Value2: 50V; TaMin_C: -55; TaMax_C: 125; Cap_Case: 0402
C37 = CGA2B3X7R1H153K050BB: CAP, CERM, 0.015 µF, 50 V, +/- 10%, X7R, AEC-Q200 Grade 1, 0402; Manufacturer: TDK; Polarized: N; CompType: Capacitor; Value: 0.015uF; U/M: EA; Cap_F: 0.000000015; Tolerance_%: 10; ESR_ohm: 0.2162; Value1: 0.2162 ohm; VDC_V: 50; Value2: 50V; IRMS_A: 0.379389; TaMin_C: -55; TaMax_C: 125; Cap_Case: 0402; SizeArea_mm2: 0.5; SizeAreaWB_mm2: 3; SizeX_mm: 1; SizeZ_mm: 0.6; AEC Category: Q200; AEC Qualified: Y
C39 C42 C46 = JMK107BB7475MA-T: CAP, CERM, 4.7 µF, 6.3 V, +/- 10%, X7R, 0603; Manufacturer: Taiyo Yuden; Polarized: N; CompType: Capacitor; Value: 4.7uF; U/M: EA; Cap_F: 0.0000047; Tolerance_%: 10; Value1: Unknown; VDC_V: 6.3; TaMin_C: -55; TaMax_C: 125; Cap_Case: 0603; SizeArea_mm2: 1.28; SizeAreaWB_mm2: 4.68; SizeX_mm: 1.6; SizeY_mm: 0.8; SizeZ_mm: 1; AEC Category: Q200
C44 = GRM155R70J223KA01D: CAP, CERM, 0.022 µF, 6.3 V, +/- 10%, X7R, 0402; Manufacturer: MuRata; Polarized: N; CompType: Capacitor; Value: 0.022uF; U/M: EA; Cap_F: 0.000000022; Tolerance_%: 10; Value1: Unknown; VDC_V: 6.3; Value2: 6.3V; TaMin_C: -55; TaMax_C: 125; Cap_Case: 0402; SizeArea_mm2: 0.5; SizeAreaWB_mm2: 3; SizeX_mm: 1; SizeZ_mm: 0.6; AEC Category: Q200
C49 = GRM155R60J474KE19D: CAP, CERM, 0.47 µF, 6.3 V, +/- 10%, X5R, 0402; Manufacturer: MuRata; Polarized: N; CompType: Capacitor; Value: 0.47uF; U/M: EA; Cap_F: 0.00000047; Tolerance_%: 10; Value1: Unknown; VDC_V: 6.3; Value2: 6.3V; TaMin_C: -55; TaMax_C: 85; Cap_Case: 0402; SizeArea_mm2: 0.5; SizeAreaWB_mm2: 3; SizeX_mm: 1; SizeZ_mm: 0.6; AEC Category: Q200
L14-L16 = BLM15AX102SN1D: as L9 on sheet Imager
R9 R10 = CRCW04023K30JNED: RES, 3.3 k, 5%, 0.063 W, 0402; Manufacturer: Vishay-Dale; CompType: Resistor; Value: 3.3k; Res_ohm: 3300; Value_Code: 3k30; Tolerance_%: 5; Power_W: 0.063; Value2: 0.063W; VDC_V: 50; TempCo: 200 ppm/C; SizeArea_mm2: 0.5; SizeX_mm: 1; SizeZ_mm: 0.6; EIA_Code: E24; U/M: EA; AEC Category: Q200
R11 R13 R14 = CRCW040210K0JNED: as R3 on sheet Coax Connection and Power Supply
R12 = CRCW040249R9FKED: RES, 49.9 ohm, 1%, 0.063W, 0402; Manufacturer: Vishay-Dale; CompType: Resistor; Value_Code: 49R9; Tolerance_%: 1; Power_W: 0.063; VDC_V: 50; TempCo: 100 ppm/C; EIA_Code: E96; U/M: EA
R15 R16 = CRCW0402402RFKED: RES, 402, 1%, 0.063 W, 0402; Manufacturer: Vishay-Dale; CompType: Resistor; Value: 402; Value_Code: 402R; Tolerance_%: 1; Power_W: 0.063; Value2: 0.063W; VDC_V: 50; TempCo: 100 ppm/C; SizeArea_mm2: 0.5; SizeZ_mm: 0.6; EIA_Code: E96; U/M: EA; AEC Category: Q200
U5 = DS90UB953QRHBQ1: FPD-Link III SerDes with CSI-2 interfaces for 2.3MP/60fps camera, RHB0032B; Manufacturer: Texas Instruments; SymbolCreator: Altium; SizeArea_mm2: 25; SizeAreaWB_mm2: 49; SizeX_mm: 5; SizeZ_mm: 1; CompType: IC; U/M: EA

## Sheet HDWR.SchDoc: Hardware
size 431 x 279 mm; Date: Not shown in title block; ApprovedBy: Not shown in title block; CheckedBy: Not shown in title block; Author: Not shown in title block; CompanyName: Not shown in title block; DrawnBy: Brian Shaffer; Engineer: Not shown in title block; Organization: Not shown in title block; Address1: Not shown in title block; Address2: Not shown in title block; Address3: Not shown in title block; Address4: Not shown in title block; DocumentNumber: 4; Revision: Use project parameter SCH_Rev; SheetNumber: 4; SheetTotal: 4; PageSetup: Record=PageOptions¦CenterHorizontal=True¦CenterVertical=True¦PrintScale=1.00¦XCorrection=1.00¦YCorrection=1.00¦PrintKind=0¦BorderSize=5000000¦LeftOffset=0¦BottomOffset=0¦Orientation=2¦PaperLength=1000¦PaperWidth=1000¦Scale=100¦PaperSource=15¦PrintQuality=600¦MediaType=1¦DitherType=10¦PaperKind=Letter¦PrintScaleMode=1
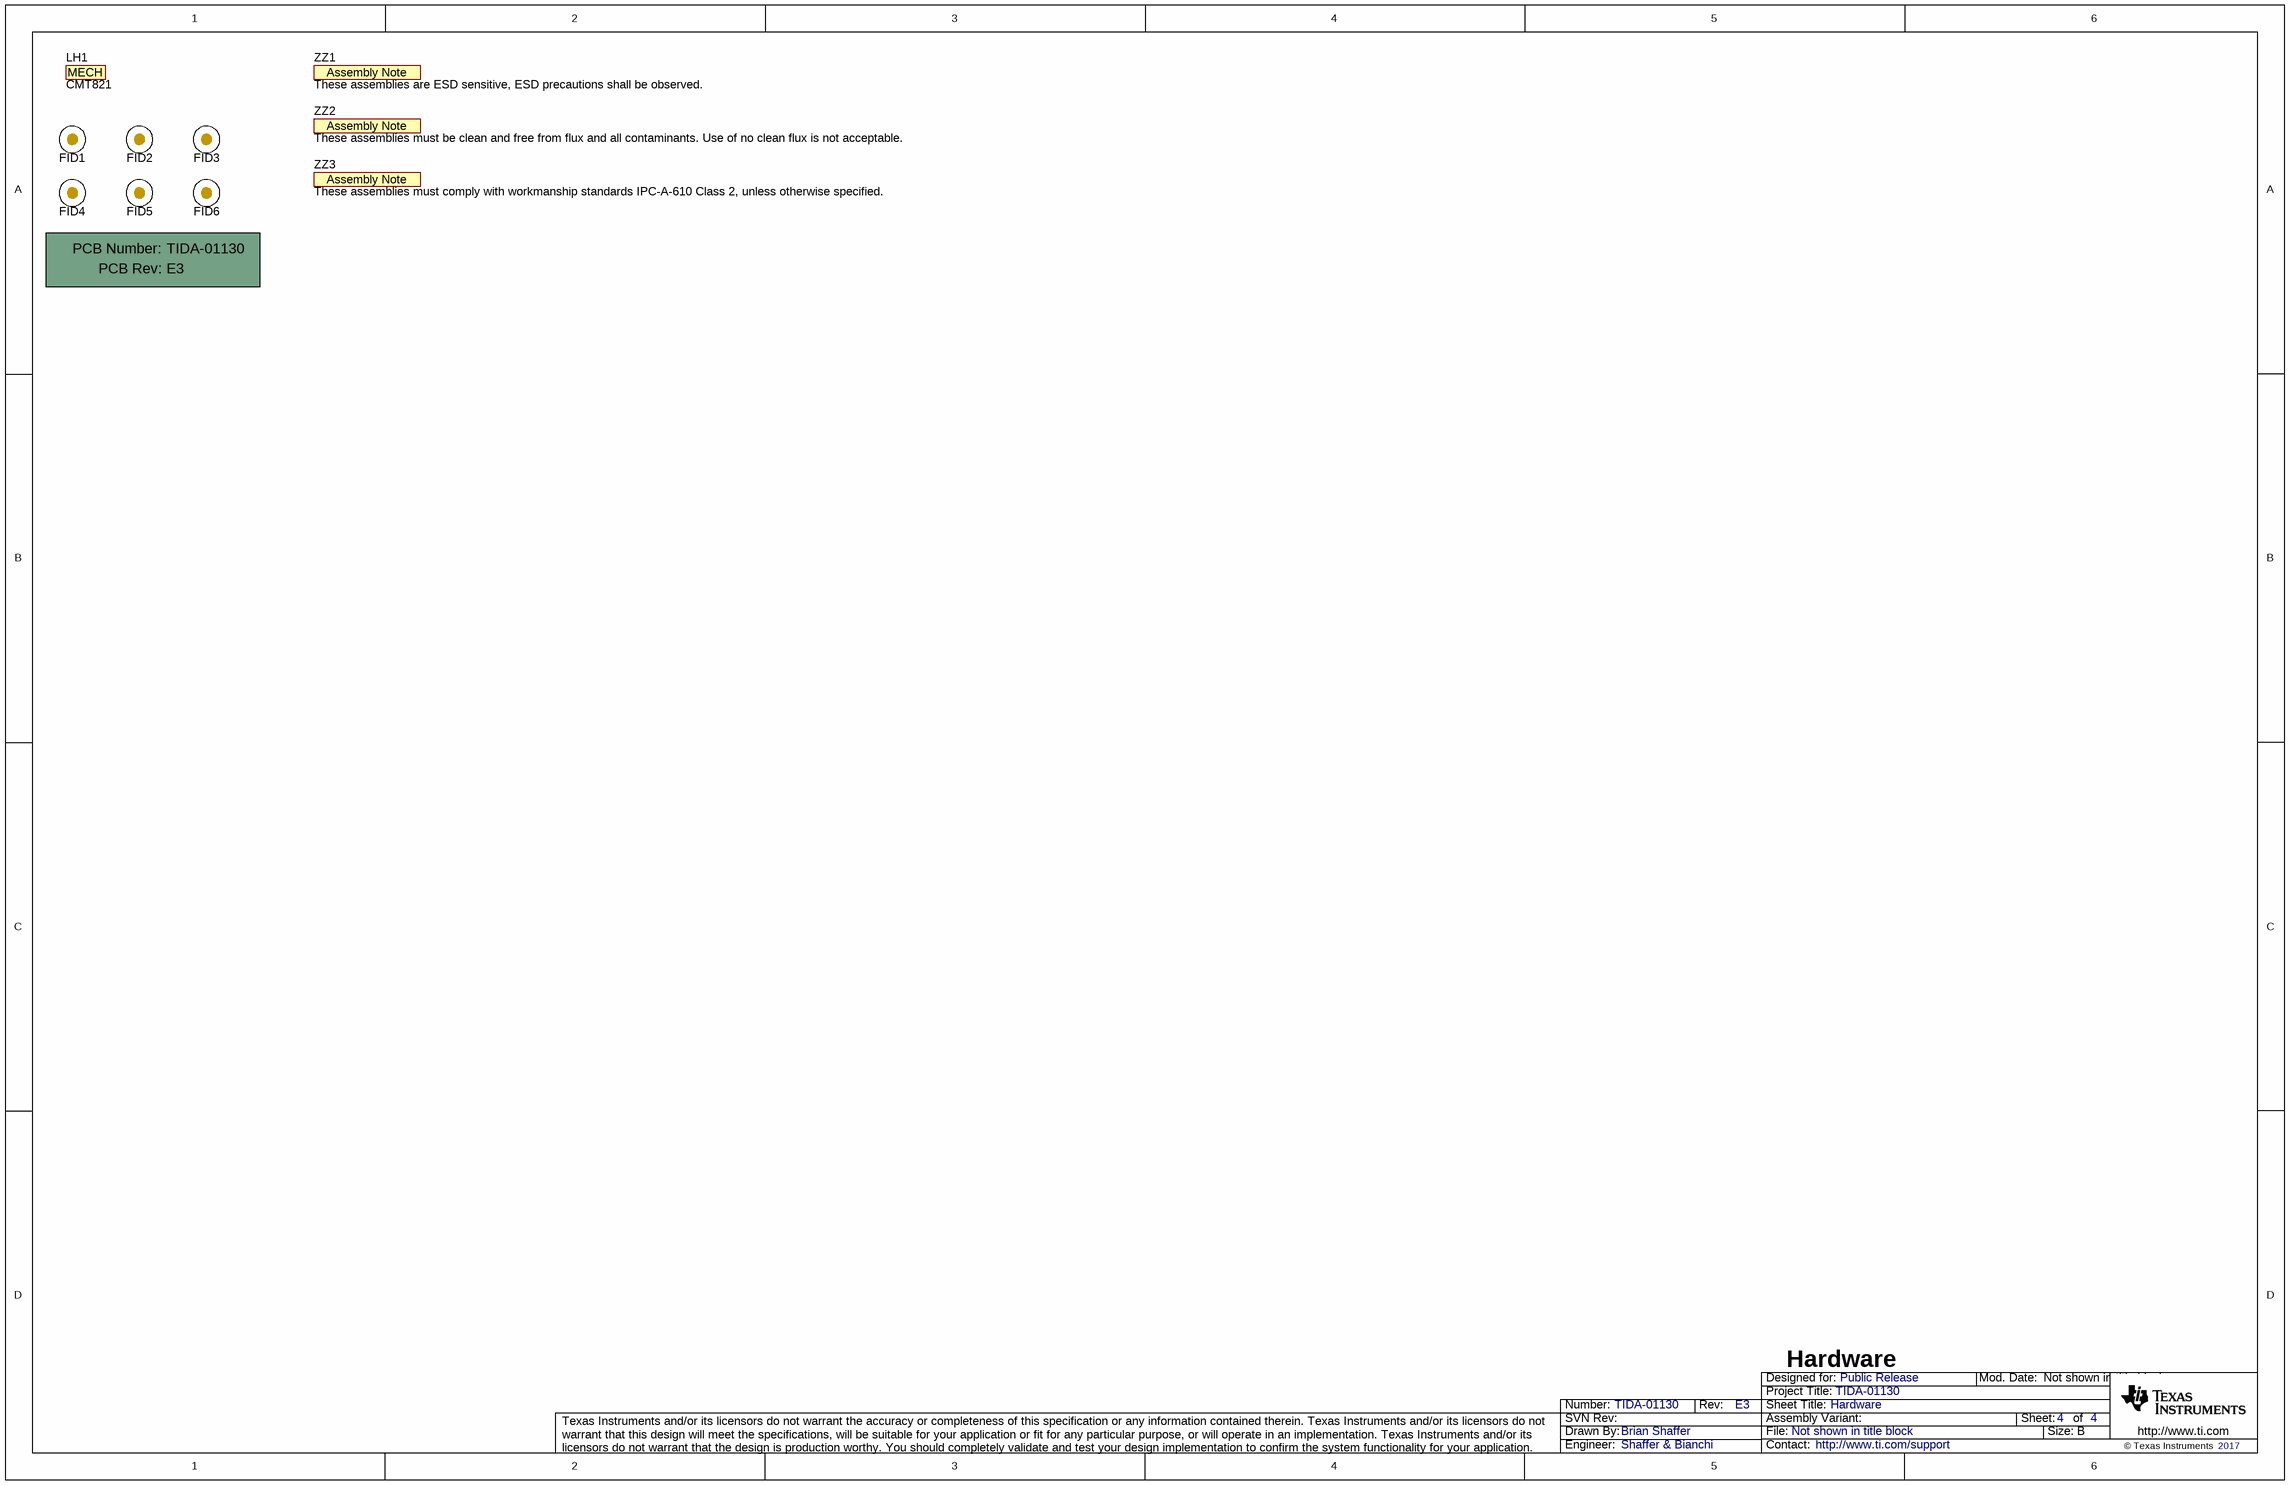
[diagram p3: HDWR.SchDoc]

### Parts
!PCB1  Printed Circuit Board  (value not drawn)  (mechanical)
FID1  Fiducial  [Fiducial10-20]  (value not drawn)
FID2  Fiducial  [Fiducial10-20]  (value not drawn)
FID3  Fiducial  [Fiducial10-20]  (value not drawn)
FID4  Fiducial  [Fiducial10-20]  (value not drawn)
FID5  Fiducial  [Fiducial10-20]  (value not drawn)
FID6  Fiducial  [Fiducial10-20]  (value not drawn)
LH1  CMT821  [CMT821]
ZZ1  These assemblies are ESD sensitive, ESD precautions shall be observed.  [AssemblyNote]  (no BOM)
ZZ2  These assemblies must be clean and free from flux and all contaminants. Use of no clean flux is not acceptable.  [AssemblyNote]  (no BOM)
ZZ3  These assemblies must comply with workmanship standards IPC-A-610 Class 2, unless otherwise specified.  [AssemblyNote]  (no BOM)

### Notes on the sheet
- Hardware

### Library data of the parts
!PCB1 = PCB: Manufacturer: Any; PartNumber: TIDA-01130; SymbolCreator: a0412235
FID1-FID6 = Fiducial: Fiducial mark.  There is nothing to buy or mount.; SymbolCreator: codlsc
LH1 = CMT821: Sunex Lens Holder; Manufacturer: Sunex Inc.
ZZ1-ZZ3 = AssemblyNote: SymbolCreator: codlsc

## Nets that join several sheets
1V3: Coax Connection and Power Supply (C3.1 U1.3), Imager (8 pins)
1V8: Coax Connection and Power Supply (C6.1 U3.3), Imager (L11.1 L12.1), Serializer (L14.1 L15.1 L16.1)
3V3: Coax Connection and Power Supply (5 pins), Imager (L9.1 L10.1)
GND: Coax Connection and Power Supply (16 pins), Imager (29 pins), Serializer (22 pins)
3V3_PG: Coax Connection and Power Supply (U2.8), Serializer (C49.1 R11.1 U5.8)
CSI0_CLK_N: Imager (U4.F5), Serializer (U5.6)
CSI0_CLK_P: Imager (U4.E5), Serializer (U5.5)
CSI0_D0_N: Imager (U4.F4), Serializer (U5.4)
CSI0_D0_P: Imager (U4.E4), Serializer (U5.3)
CSI0_D1_N: Imager (U4.F6), Serializer (U5.2)
CSI0_D1_P: Imager (U4.E6), Serializer (U5.1)
CSI0_D2_N: Imager (U4.F3), Serializer (U5.32)
CSI0_D2_P: Imager (U4.E3), Serializer (U5.31)
CSI0_D3_N: Imager (U4.F7), Serializer (U5.30)
CSI0_D3_P: Imager (U4.E7), Serializer (U5.29)
DOUTP_F: Coax Connection and Power Supply (L2.1 P1.1), Serializer (C36.1)
FSIN: Imager (U4.D10), Serializer (U5.18)
n_IMAGER_PWDN: Imager (U4.D3), Serializer (U5.27)
n_IMAGER_RESET: Imager (U4.F10), Serializer (U5.28)
SCL: Imager (U4.E9), Serializer (R9.1 U5.24)
SDA: Imager (U4.F9), Serializer (R10.1 U5.23)
VSYNC: Imager (R8.2 U4.G8), Serializer (U5.17)
XCLK: Imager (U4.G1), Serializer (R13.1 R15.2 U5.19)

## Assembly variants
001: not fitted FID1 FID2 FID3 FID4 FID5 FID6 L7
